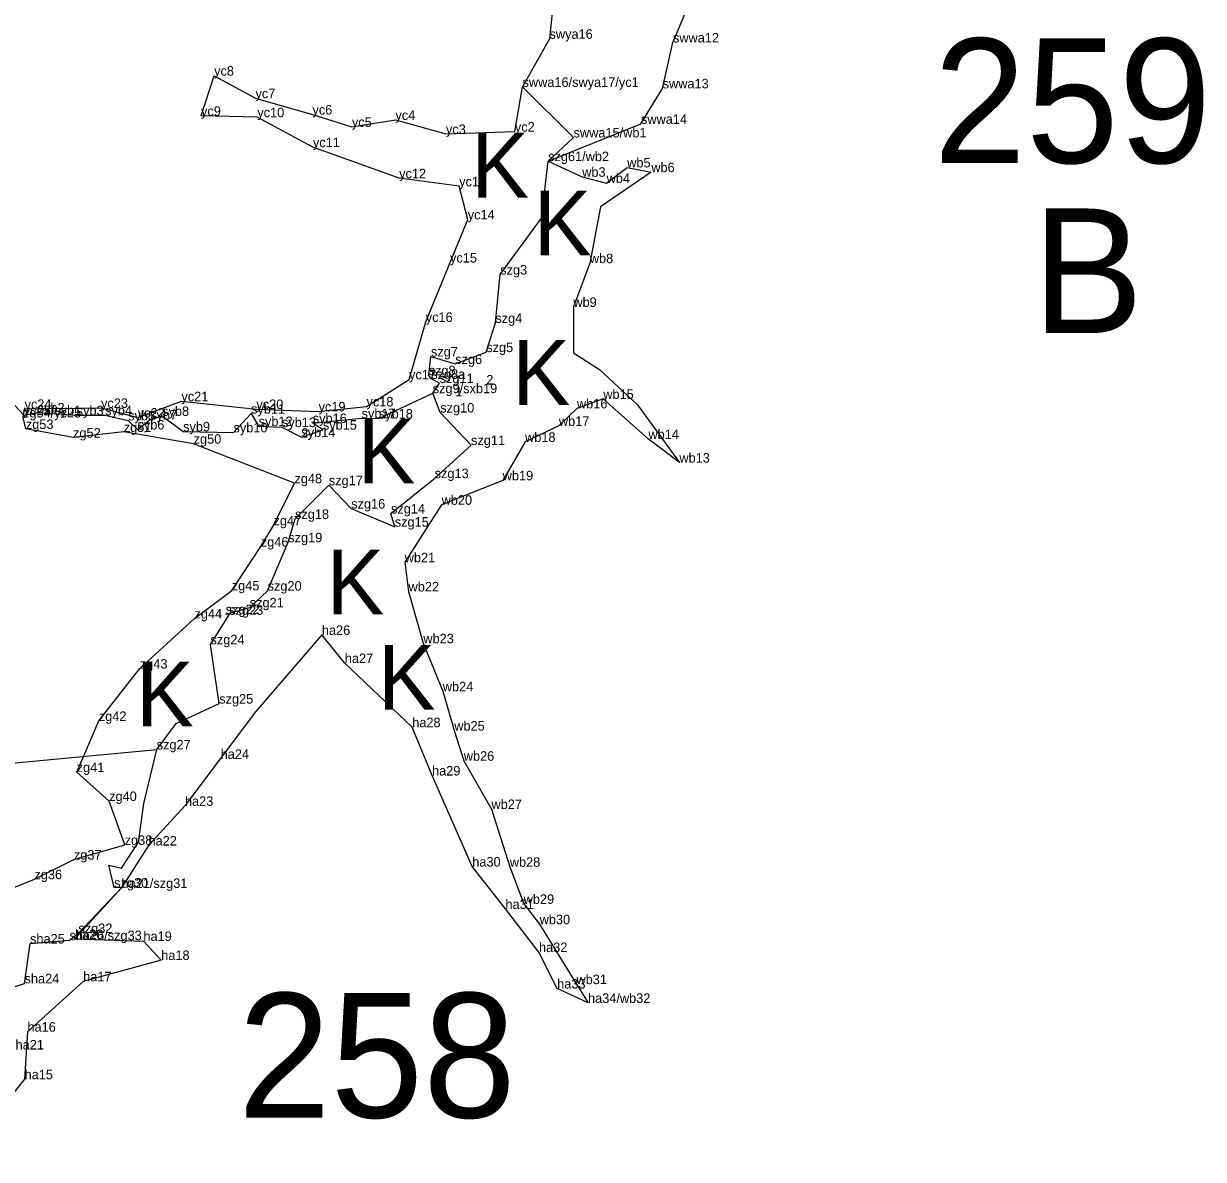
# Model space of a CAD drawing. Extents: x 2072529 to 2268796, y 436423 to 470406.
# Drawn here: x 2217671 to 2218290, y 438347 to 438943 of the extents above; entities that cross this region are included whole.
import ezdxf

# ---------------------------------------------------------------- set-up
doc = ezdxf.new("R2010")
doc.units = 0
for name, color, linetype in [('Default', 7, 'Continuous'), ('Exist Environmental Wetland Boundary Cogo Comment', 7, 'Continuous'), ('Exist Environmental Wetland Boundary Cogo Point CELL', 7, 'Continuous'), ('Exist Hydro Jurisdictional Stream or Body of Water NEU Mitigable Cogo Comment', 7, 'Continuous'), ('Old_Level_20', 7, 'Continuous'), ('Old_Level_52', 7, 'Continuous')]:
    doc.layers.add(name, color=color, linetype=linetype)

msp = doc.modelspace()

# ---------------------------------------------------------------- linework, layer by layer
at = {"layer": 'Default'}
for p, q in [((2217636.33, 438774.91), (2217671.41, 438737.63)), ((2217544.84, 438543.82), (2217741.11, 438562.25))]:
    msp.add_line(p, q, dxfattribs=at)
at = {"layer": 'Old_Level_20'}
for p, q in [((2217947.25, 438934.98), (2217947.25, 438934.98)), ((2218012.02, 438933.04), (2218012.02, 438933.04)), ((2217771.26, 438915.63), (2217771.26, 438915.63)), ((2217933.09, 438909.73), (2217933.09, 438909.73)), ((2217933.09, 438909.73), (2217933.09, 438909.73)), ((2218006.61, 438908.97), (2218006.61, 438908.97)), ((2217792.96, 438903.78), (2217792.96, 438903.78)), ((2217764.38, 438894.56), (2217764.38, 438894.56)), ((2217793.91, 438893.84), (2217793.91, 438893.84)), ((2217822.84, 438895.26), (2217822.84, 438895.26)), ((2217866.37, 438892.43), (2217866.37, 438892.43)), ((2217995.23, 438890.36), (2217995.23, 438890.36)), ((2217843.55, 438888.8), (2217843.55, 438888.8)), ((2217892.9, 438885.05), (2217892.9, 438885.05)), ((2217929.08, 438886.27), (2217929.08, 438886.27)), ((2217959.87, 438883.23), (2217959.87, 438883.23)), ((2217959.87, 438883.23), (2217959.87, 438883.23)), ((2217823.08, 438878.14), (2217823.08, 438878.14)), ((2217946.5, 438870.8), (2217946.5, 438870.8)), ((2217946.5, 438870.8), (2217946.5, 438870.8)), ((2217988, 438867.51), (2217988, 438867.51)), ((2218000.66, 438865.02), (2218000.66, 438865.02)), ((2217868.34, 438861.82), (2217868.34, 438861.82)), ((2217964.4, 438862.6), (2217964.4, 438862.6)), ((2217977.21, 438859.33), (2217977.21, 438859.33)), ((2217899.83, 438857.62), (2217899.83, 438857.62)), ((2217904.35, 438840.25), (2217904.35, 438840.25)), ((2217895.04, 438817.63), (2217895.04, 438817.63)), ((2217968.39, 438817.3), (2217968.39, 438817.3)), ((2217921.39, 438811.3), (2217921.39, 438811.3)), ((2217959.76, 438794.33), (2217959.76, 438794.33)), ((2217882.3, 438786.48), (2217882.3, 438786.48)), ((2217918.81, 438785.95), (2217918.81, 438785.95)), ((2217885.04, 438768.35), (2217885.04, 438768.35)), ((2217914.05, 438770.65), (2217914.05, 438770.65)), ((2217897.76, 438764.41), (2217897.76, 438764.41)), ((2217873.53, 438756.36), (2217873.53, 438756.36)), ((2217883.84, 438758.54), (2217883.84, 438758.54)), ((2217885.17, 438756.6), (2217885.17, 438756.6)), ((2217889.58, 438754.39), (2217889.58, 438754.39)), ((2217885.95, 438749.1), (2217885.95, 438749.1)), ((2217671.78, 438740.85), (2217671.78, 438740.85)), ((2217711.9, 438741.36), (2217711.9, 438741.36)), ((2217754.08, 438744.89), (2217754.08, 438744.89)), ((2217793.42, 438740.78), (2217793.42, 438740.78)), ((2217851.21, 438742.14), (2217851.21, 438742.14)), ((2217961.62, 438741.12), (2217961.62, 438741.12)), ((2217975.44, 438746.08), (2217975.44, 438746.08)), ((2217671.41, 438737.63), (2217671.41, 438737.63)), ((2217678.68, 438738.96), (2217678.68, 438738.96)), ((2217699.14, 438737.49), (2217699.14, 438737.49)), ((2217714.03, 438737.53), (2217714.03, 438737.53)), ((2217726.13, 438734.84), (2217726.13, 438734.84)), ((2217731.17, 438736.28), (2217731.17, 438736.28)), ((2217737.7, 438735.26), (2217737.7, 438735.26)), ((2217743.98, 438737.16), (2217743.98, 438737.16)), ((2217790.62, 438738.38), (2217790.62, 438738.38)), ((2217826.06, 438739.52), (2217826.06, 438739.52)), ((2217848.63, 438735.95), (2217848.63, 438735.95)), ((2217857.69, 438735.78), (2217857.69, 438735.78)), ((2217889.9, 438738.97), (2217889.9, 438738.97)), ((2217672.46, 438730.32), (2217672.46, 438730.32)), ((2217723.84, 438728.75), (2217723.84, 438728.75)), ((2217731.05, 438730.04), (2217731.05, 438730.04)), ((2217754.98, 438729.06), (2217754.98, 438729.06)), ((2217781.43, 438728.55), (2217781.43, 438728.55)), ((2217794.6, 438731.84), (2217794.6, 438731.84)), ((2217806.86, 438731.31), (2217806.86, 438731.31)), ((2217823.01, 438733.44), (2217823.01, 438733.44)), ((2217828.32, 438729.95), (2217828.32, 438729.95)), ((2217952.17, 438731.95), (2217952.17, 438731.95)), ((2217697.22, 438725.8), (2217697.22, 438725.8)), ((2217760.51, 438722.59), (2217760.51, 438722.59)), ((2217817.02, 438726.09), (2217817.02, 438726.09)), ((2217934.39, 438723.56), (2217934.39, 438723.56)), ((2217999.14, 438725.02), (2217999.14, 438725.02)), ((2217906.08, 438721.89), (2217906.08, 438721.89)), ((2218015.38, 438712.67), (2218015.38, 438712.67)), ((2217886.98, 438704.54), (2217886.98, 438704.54)), ((2217813.4, 438701.83), (2217813.4, 438701.83)), ((2217831.43, 438700.84), (2217831.43, 438700.84)), ((2217922.67, 438703.38), (2217922.67, 438703.38)), ((2217843.19, 438688.59), (2217843.19, 438688.59)), ((2217864.06, 438685.99), (2217864.06, 438685.99)), ((2217890.61, 438690.57), (2217890.61, 438690.57)), ((2217802.43, 438679.75), (2217802.43, 438679.75)), ((2217813.7, 438683.16), (2217813.7, 438683.16)), ((2217866.04, 438679.08), (2217866.04, 438679.08)), ((2217795.78, 438668.61), (2217795.78, 438668.61)), ((2217810.15, 438670.89), (2217810.15, 438670.89)), ((2217871.26, 438660.41), (2217871.26, 438660.41)), ((2217780.52, 438645.68), (2217780.52, 438645.68)), ((2217799.31, 438645.52), (2217799.31, 438645.52)), ((2217873.28, 438645.11), (2217873.28, 438645.11)), ((2217789.94, 438636.76), (2217789.94, 438636.76)), ((2217760.94, 438630.93), (2217760.94, 438630.93)), ((2217777.31, 438633.2), (2217777.31, 438633.2)), ((2217779.18, 438632.86), (2217779.18, 438632.86)), ((2217769.35, 438617.37), (2217769.35, 438617.37)), ((2217827.79, 438622.29), (2217827.79, 438622.29)), ((2217881.02, 438617.93), (2217881.02, 438617.93)), ((2217732.28, 438604.63), (2217732.28, 438604.63)), ((2217839.82, 438607.56), (2217839.82, 438607.56)), ((2217891.24, 438592.74), (2217891.24, 438592.74)), ((2217773.92, 438586.27), (2217773.92, 438586.27)), ((2217710.75, 438577.17), (2217710.75, 438577.17)), ((2217875.21, 438573.89), (2217875.21, 438573.89)), ((2217897.26, 438572.14), (2217897.26, 438572.14)), ((2217741.11, 438562.25), (2217741.11, 438562.25)), ((2217774.68, 438557.3), (2217774.68, 438557.3)), ((2217902.25, 438556.31), (2217902.25, 438556.31)), ((2217699.13, 438550.35), (2217699.13, 438550.35)), ((2217885.6, 438548.57), (2217885.6, 438548.57)), ((2217716.18, 438535.18), (2217716.18, 438535.18)), ((2217755.94, 438532.64), (2217755.94, 438532.64)), ((2217916.77, 438530.99), (2217916.77, 438530.99)), ((2217724.32, 438512.19), (2217724.32, 438512.19)), ((2217736.81, 438511.86), (2217736.81, 438511.86)), ((2217697.67, 438504.47), (2217697.67, 438504.47)), ((2217906.71, 438500.8), (2217906.71, 438500.8)), ((2217926.41, 438500.68), (2217926.41, 438500.68)), ((2217676.96, 438494.19), (2217676.96, 438494.19)), ((2217718.8, 438489.79), (2217718.8, 438489.79)), ((2217722.64, 438489.58), (2217722.64, 438489.58)), ((2217722.64, 438489.58), (2217722.64, 438489.58)), ((2217933.69, 438481.24), (2217933.69, 438481.24)), ((2217924.13, 438478.56), (2217924.13, 438478.56)), ((2217942.06, 438470.55), (2217942.06, 438470.55)), ((2217695.34, 438462.22), (2217695.34, 438462.22)), ((2217698.23, 438462.74), (2217698.23, 438462.74)), ((2217700.03, 438465.94), (2217700.03, 438465.94)), ((2217674.66, 438460.46), (2217674.66, 438460.46)), ((2217734.16, 438461.77), (2217734.16, 438461.77)), ((2217743.49, 438451.8), (2217743.49, 438451.8)), ((2217941.72, 438455.97), (2217941.72, 438455.97)), ((2217671.77, 438439.56), (2217671.77, 438439.56)), ((2217702.54, 438440.61), (2217702.54, 438440.61)), ((2217961.38, 438439.14), (2217961.38, 438439.14)), ((2217951.26, 438436.82), (2217951.26, 438436.82)), ((2217967.44, 438429.29), (2217967.44, 438429.29)), ((2217673.28, 438414.22), (2217673.28, 438414.22)), ((2217671.8, 438389.27), (2217671.8, 438389.27))]:
    msp.add_line(p, q, dxfattribs=at)
for points in [[(2217650.1, 438483.36), (2217676.96, 438494.19), (2217697.67, 438504.47), (2217724.32, 438512.19), (2217716.18, 438535.18), (2217699.13, 438550.35), (2217710.75, 438577.17), (2217732.28, 438604.63), (2217760.94, 438630.93), (2217780.52, 438645.68), (2217795.78, 438668.61), (2217802.43, 438679.75), (2217813.4, 438701.83), (2217760.51, 438722.59), (2217723.84, 438728.75), (2217697.22, 438725.8), (2217672.46, 438730.32), (2217671, 438736.35), (2217671.78, 438740.85), (2217711.9, 438741.36), (2217731.17, 438736.28), (2217754.08, 438744.89), (2217793.42, 438740.78), (2217826.06, 438739.52), (2217851.21, 438742.14), (2217873.53, 438756.36), (2217882.3, 438786.48), (2217895.04, 438817.63), (2217904.35, 438840.25), (2217899.83, 438857.62), (2217868.34, 438861.82), (2217823.08, 438878.14), (2217793.91, 438893.84), (2217764.38, 438894.56), (2217771.26, 438915.63), (2217792.96, 438903.78), (2217822.84, 438895.26), (2217843.55, 438888.8), (2217866.37, 438892.43), (2217892.9, 438885.05), (2217929.08, 438886.27), (2217933.09, 438909.73)], [(2217959.87, 438883.23), (2217946.5, 438870.8), (2217964.4, 438862.6), (2217977.21, 438859.33), (2217988, 438867.51), (2218000.66, 438865.02), (2217974.07, 438846.77), (2217968.39, 438817.3), (2217959.76, 438794.33), (2217959.88, 438770.28), (2217973.44, 438761.55), (2217993.4, 438742.94), (2218015.38, 438712.67), (2217999.14, 438725.02), (2217975.44, 438746.08), (2217961.62, 438741.12), (2217952.17, 438731.95), (2217934.39, 438723.56), (2217922.67, 438703.38), (2217890.61, 438690.57), (2217871.26, 438660.41), (2217873.28, 438645.11), (2217881.02, 438617.93), (2217891.24, 438592.74), (2217897.26, 438572.14), (2217902.25, 438556.31), (2217916.77, 438530.99), (2217926.41, 438500.68), (2217933.69, 438481.24), (2217942.06, 438470.55), (2217961.38, 438439.14), (2217967.44, 438429.29), (2217951.26, 438436.82), (2217941.72, 438455.97), (2217924.13, 438478.56), (2217906.71, 438500.8), (2217885.6, 438548.57), (2217875.21, 438573.89), (2217839.82, 438607.56), (2217827.79, 438622.29), (2217792.98, 438581.97), (2217755.94, 438532.64), (2217736.81, 438511.86), (2217722.64, 438489.58), (2217698.23, 438462.84), (2217734.16, 438461.77), (2217743.49, 438451.8), (2217702.54, 438440.61), (2217673.28, 438414.22), (2217671.8, 438389.27), (2217638.07, 438347.23)]]:
    msp.add_lwpolyline(points, dxfattribs=at)
at = {"layer": 'Old_Level_52'}
for points in [[(2217951.55, 438977.67), (2217947.25, 438934.98), (2217933.09, 438909.73), (2217959.87, 438883.23), (2217946.5, 438870.8), (2217995.23, 438890.36), (2218006.61, 438908.97), (2218012.02, 438933.04), (2218026.19, 438966.68)], [(2217653.35, 438433.79), (2217671.77, 438439.56), (2217674.66, 438460.46), (2217695.34, 438462.22), (2217700.03, 438465.94), (2217722.64, 438489.58), (2217718.8, 438489.79), (2217715.94, 438501.57), (2217722.61, 438499.98), (2217731.52, 438513.6), (2217734.44, 438533.91), (2217741.11, 438562.25), (2217751.33, 438575.89), (2217773.92, 438586.27), (2217769.35, 438617.37), (2217779.18, 438632.86), (2217777.31, 438633.2), (2217789.94, 438636.76), (2217799.31, 438645.52), (2217810.15, 438670.89), (2217813.7, 438683.16), (2217831.43, 438700.84), (2217843.19, 438688.59), (2217866.04, 438679.08), (2217864.06, 438685.99), (2217886.98, 438704.54), (2217906.08, 438721.89), (2217889.9, 438738.97), (2217885.95, 438749.1), (2217889.58, 438754.39), (2217885.17, 438756.6), (2217883.84, 438758.54), (2217885.04, 438768.35), (2217897.76, 438764.41), (2217914.05, 438770.65), (2217918.81, 438785.95), (2217921.39, 438811.3), (2217943.04, 438840.96), (2217946.5, 438870.8)], [(2217671.41, 438737.63), (2217678.68, 438738.96), (2217699.14, 438737.49), (2217714.03, 438737.53), (2217726.13, 438734.84), (2217731.05, 438730.04), (2217737.7, 438735.26), (2217743.98, 438737.16), (2217754.98, 438729.06), (2217781.43, 438728.55), (2217790.62, 438738.38), (2217794.6, 438731.84), (2217806.86, 438731.31), (2217817.02, 438726.09), (2217828.32, 438729.95), (2217823.01, 438733.44), (2217848.63, 438735.95), (2217857.69, 438735.78), (2217885.95, 438749.1)]]:
    msp.add_lwpolyline(points, dxfattribs=at)

# ---------------------------------------------------------------- texts
at = {"layer": 'Default'}
for s, p in [('259', (2218148.71, 438869.8)), ('B', (2218200.53, 438780.64)), ('258', (2217783.77, 438369.14))]:
    msp.add_text(s, height=65.34, dxfattribs=at).set_placement(p)
at = {"layer": 'Exist Environmental Wetland Boundary Cogo Comment'}
for s, p in [('yc8', (2217771.26, 438915.63)), ('yc7', (2217792.96, 438903.78)), ('yc9', (2217764.38, 438894.56)), ('yc10', (2217793.91, 438893.84)), ('yc6', (2217822.84, 438895.26)), ('yc4', (2217866.37, 438892.43)), ('yc5', (2217843.55, 438888.8)), ('yc3', (2217892.9, 438885.05)), ('yc2', (2217929.08, 438886.27)), ('yc11', (2217823.08, 438878.14)), ('wb5', (2217988, 438867.51)), ('yc12', (2217868.34, 438861.82)), ('wb3', (2217964.4, 438862.6)), ('wb4', (2217977.21, 438859.33)), ('wb6', (2218000.66, 438865.02)), ('yc13', (2217899.83, 438857.62)), ('yc14', (2217904.35, 438840.25)), ('yc15', (2217895.04, 438817.63)), ('wb8', (2217968.39, 438817.3)), ('wb9', (2217959.76, 438794.33)), ('yc16', (2217882.3, 438786.48)), ('yc17', (2217873.53, 438756.36)), ('yc21', (2217754.08, 438744.89)), ('yc18', (2217851.21, 438742.14)), ('wb15', (2217975.44, 438746.08)), ('zg54/yc25', (2217671, 438736.35)), ('yc24', (2217671.78, 438740.85)), ('yc23', (2217711.9, 438741.36)), ('yc20', (2217793.42, 438740.78)), ('yc19', (2217826.06, 438739.52)), ('wb16', (2217961.62, 438741.12)), ('zg53', (2217672.46, 438730.32)), ('wb17', (2217952.17, 438731.95)), ('zg52', (2217697.22, 438725.8)), ('zg51', (2217723.84, 438728.75)), ('wb18', (2217934.39, 438723.56)), ('wb14', (2217999.14, 438725.02)), ('zg50', (2217760.51, 438722.59)), ('wb13', (2218015.38, 438712.67)), ('zg48', (2217813.4, 438701.83)), ('wb19', (2217922.67, 438703.38)), ('wb20', (2217890.61, 438690.57)), ('zg47', (2217802.43, 438679.75)), ('zg46', (2217795.78, 438668.61)), ('wb21', (2217871.26, 438660.41)), ('zg45', (2217780.52, 438645.68)), ('wb22', (2217873.28, 438645.11)), ('zg44', (2217760.94, 438630.93)), ('ha26', (2217827.79, 438622.29)), ('wb23', (2217881.02, 438617.93)), ('ha27', (2217839.82, 438607.56)), ('zg43', (2217732.28, 438604.63)), ('wb24', (2217891.24, 438592.74)), ('zg42', (2217710.75, 438577.17)), ('ha28', (2217875.21, 438573.89)), ('wb25', (2217897.26, 438572.14)), ('ha24', (2217774.68, 438557.3)), ('wb26', (2217902.25, 438556.31)), ('zg41', (2217699.13, 438550.35)), ('ha29', (2217885.6, 438548.57)), ('zg40', (2217716.18, 438535.18)), ('ha23', (2217755.94, 438532.64)), ('wb27', (2217916.77, 438530.99)), ('zg37', (2217697.67, 438504.47)), ('ha30', (2217906.71, 438500.8)), ('wb28', (2217926.41, 438500.68)), ('zg36', (2217676.96, 438494.19)), ('szg30', (2217718.8, 438489.79)), ('ha31', (2217924.13, 438478.56)), ('wb29', (2217933.69, 438481.24)), ('wb30', (2217942.06, 438470.55)), ('ha20', (2217698.23, 438462.84)), ('ha19', (2217734.16, 438461.77)), ('ha18', (2217743.49, 438451.8)), ('ha32', (2217941.72, 438455.97)), ('ha17', (2217702.54, 438440.61)), ('wb31', (2217961.38, 438439.14)), ('ha33', (2217951.26, 438436.82)), ('ha34/wb32', (2217967.44, 438429.29)), ('ha16', (2217673.28, 438414.22)), ('ha15', (2217671.8, 438389.27))]:
    msp.add_text(s, height=5, dxfattribs=at).set_placement(p)
at = {"layer": 'Exist Environmental Wetland Boundary Cogo Point CELL'}
for p in [(2217906.14, 438851.7), (2217938.94, 438821.4), (2217927.7, 438742.99), (2217846.48, 438701.76), (2217830.23, 438633.03), (2217857.1, 438583.05), (2217730.27, 438574.3)]:
    msp.add_text('K', height=34, dxfattribs=at).set_placement(p)
at = {"layer": 'Exist Hydro Jurisdictional Stream or Body of Water NEU Mitigable Cogo Comment'}
for s, p in [('swya16', (2217947.25, 438934.98)), ('swwa12', (2218012.02, 438933.04)), ('swwa16/swya17/yc1', (2217933.09, 438909.73)), ('swwa13', (2218006.61, 438908.97)), ('swwa14', (2217995.23, 438890.36)), ('swwa15/wb1', (2217959.87, 438883.23)), ('szg61/wb2', (2217946.5, 438870.8)), ('szg3', (2217921.39, 438811.3)), ('szg4', (2217918.81, 438785.95)), ('szg7', (2217885.04, 438768.35)), ('szg5', (2217914.05, 438770.65)), ('szg6', (2217897.76, 438764.41)), ('szg8', (2217883.84, 438758.54)), ('szg8a', (2217885.17, 438756.6)), ('szg11', (2217889.58, 438754.39)), ('szg9/sxb19', (2217885.95, 438749.1)), ('2', (2217914.05, 438753.65)), ('1', (2217897.76, 438747.41)), ('yc25/syb1', (2217671.41, 438737.63)), ('syb2', (2217678.68, 438738.96)), ('syb3', (2217699.14, 438737.49)), ('syb4', (2217714.03, 438737.53)), ('yc22', (2217731.17, 438736.28)), ('syb8', (2217743.98, 438737.16)), ('syb11', (2217790.62, 438738.38)), ('syb17', (2217848.63, 438735.95)), ('syb18', (2217857.69, 438735.78)), ('szg10', (2217889.9, 438738.97)), ('syb5', (2217726.13, 438734.84)), ('syb6', (2217731.05, 438730.04)), ('syb7', (2217737.7, 438735.26)), ('syb12', (2217794.6, 438731.84)), ('syb13', (2217806.86, 438731.31)), ('syb16', (2217823.01, 438733.44)), ('syb15', (2217828.32, 438729.95)), ('syb9', (2217754.98, 438729.06)), ('syb10', (2217781.43, 438728.55)), ('syb14', (2217817.02, 438726.09)), ('2', (2217817.02, 438725.71)), ('szg11', (2217906.08, 438721.89)), ('szg17', (2217831.43, 438700.84)), ('szg13', (2217886.98, 438704.54)), ('szg16', (2217843.19, 438688.59)), ('szg18', (2217813.7, 438683.16)), ('szg14', (2217864.06, 438685.99)), ('szg15', (2217866.04, 438679.08)), ('szg19', (2217810.15, 438670.89)), ('szg20', (2217799.31, 438645.52)), ('szg21', (2217789.94, 438636.76)), ('szg22', (2217777.31, 438633.2)), ('szg23', (2217779.18, 438632.86)), ('szg24', (2217769.35, 438617.37)), ('szg25', (2217773.92, 438586.27)), ('szg27', (2217741.11, 438562.25)), ('zg38', (2217724.32, 438512.19)), ('ha22', (2217736.81, 438511.86)), ('ha21/szg31', (2217722.64, 438489.58)), ('szg32', (2217700.03, 438465.94)), ('sha25', (2217674.66, 438460.46)), ('sha26/szg33', (2217695.34, 438462.22)), ('sha24', (2217671.77, 438439.56)), ('sha21', (2217663.72, 438404.86))]:
    msp.add_text(s, height=5, dxfattribs=at).set_placement(p)

doc.saveas('drawing.dxf')
